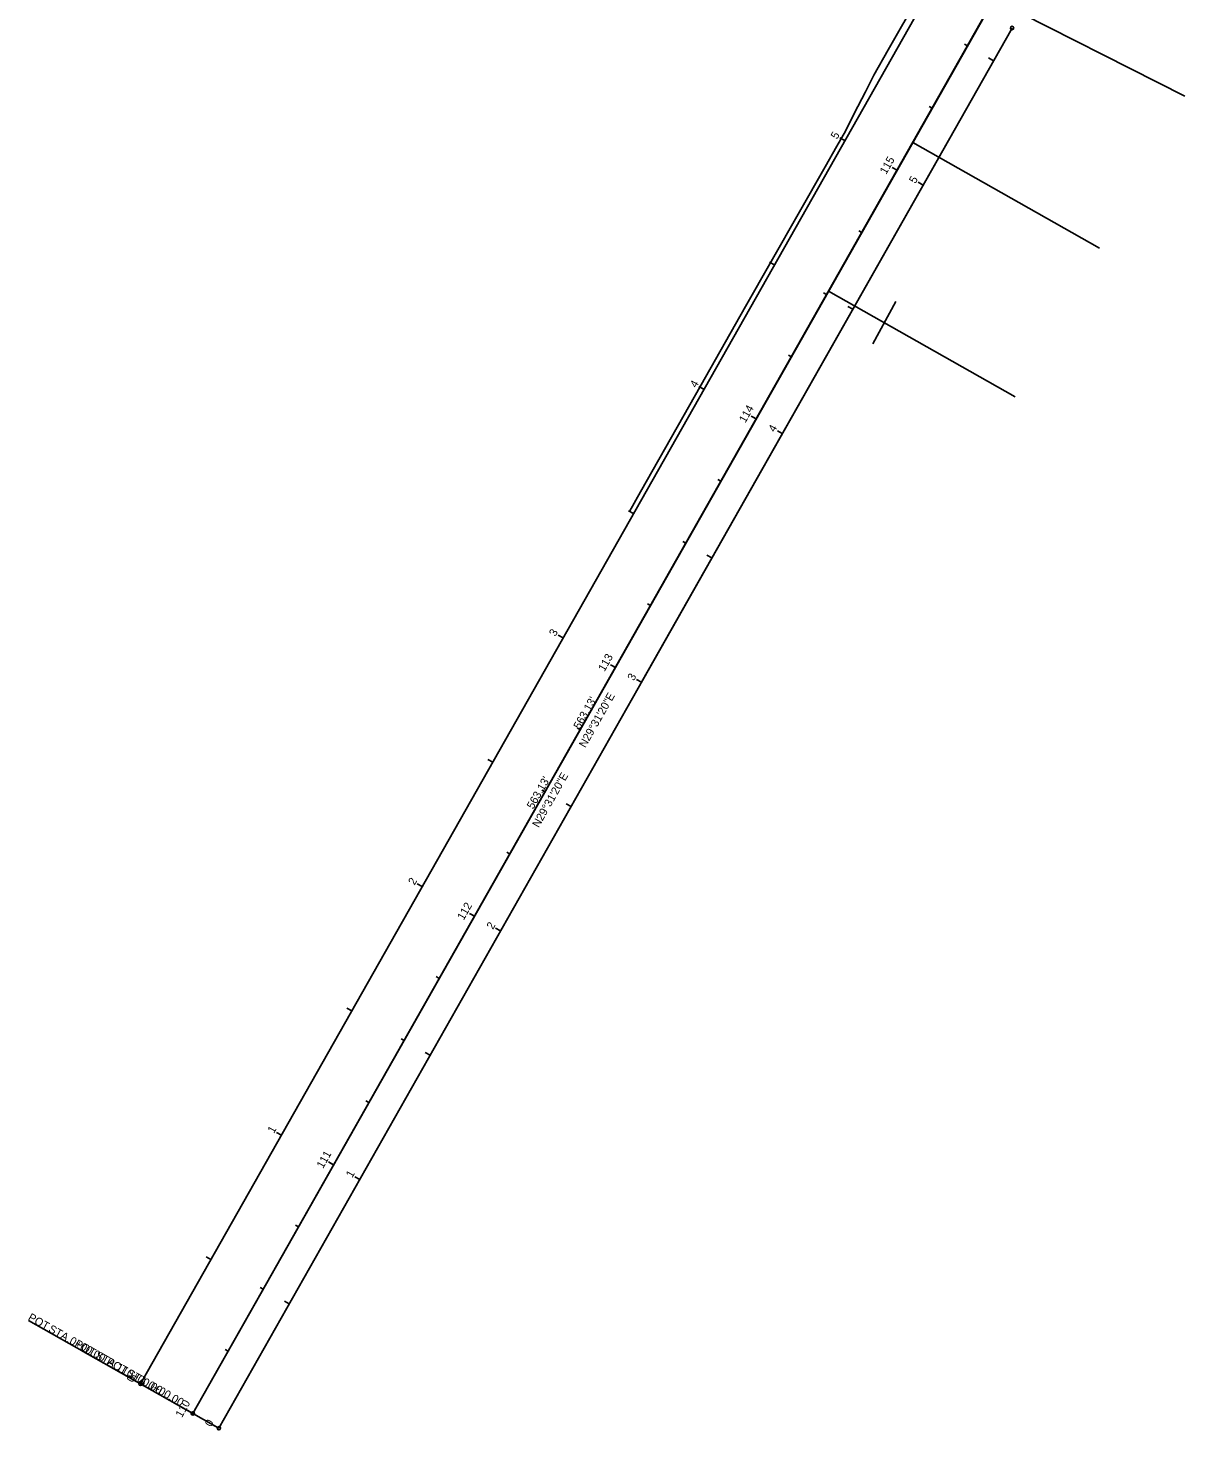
# Model space of a CAD drawing. Extents: x 1363416 to 1365241, y 422393 to 423801.
# Drawn here: x 1363842.2 to 1364246.9, y 422393.2 to 422883.8 of the extents above; entities that cross this region are included whole.
import ezdxf

# ---------------------------------------------------------------- set-up
doc = ezdxf.new("R2010")
doc.units = 0
for name, color, linetype in [('_CIVIL_CONSTRUCTION', 7, 'Continuous'), ('Default', 7, 'Continuous'), ('DT_X_Break_Line', 7, 'Continuous'), ('DT_X_Contour_Major', 7, 'Continuous'), ('DT_X_Contour_Minor', 7, 'Continuous'), ('DT_X_Island', 7, 'Continuous'), ('DT_X_Triangles', 7, 'Continuous'), ('MD_P_CURB_FACE_FL', 7, 'Continuous'), ('MD_P_CURB_FACE_TOP', 7, 'Continuous'), ('MD_P_PGL', 7, 'Continuous'), ('MD_P_SAWCUT', 7, 'Continuous'), ('PF_X_Ground_Line', 7, 'Continuous')]:
    doc.layers.add(name, color=color, linetype=linetype)

msp = doc.modelspace()

# ---------------------------------------------------------------- linework, layer by layer
at = {"layer": '_CIVIL_CONSTRUCTION'}
msp.add_line((1363899.82, 422398.95), (1364177.31, 422888.96), dxfattribs=at)
at = {"layer": 'Default'}
for p, q in [((1363899.82, 422398.95), (1364232.49, 422986.41)), ((1364145.75, 422788.04), (1364137.78, 422773.25))]:
    msp.add_line(p, q, dxfattribs=at)
at = {"layer": 'DT_X_Break_Line'}
for p, q in [((1363881.54, 422409.29), (1364159.03, 422899.31)), ((1363881.54, 422409.29), (1364159.03, 422899.31)), ((1364143.09, 422876.17), (1364154.79, 422896.72)), ((1363908.95, 422393.77), (1364186.44, 422883.79)), ((1363908.95, 422393.77), (1364186.44, 422883.79)), ((1363908.95, 422393.77), (1364186.44, 422883.79)), ((1364056.78, 422654.82), (1364186.44, 422883.79)), ((1364056.78, 422654.82), (1364186.44, 422883.79)), ((1364138.03, 422867.25), (1364143.09, 422876.17)), ((1364179.97, 422872.36), (1364178.23, 422873.35)), ((1364135.11, 422861.49), (1364138.03, 422867.25)), ((1364131.23, 422853.85), (1364135.11, 422861.49)), ((1364128.13, 422847.75), (1364131.23, 422853.85)), ((1364125.19, 422842.4), (1364128.13, 422847.75)), ((1364121.01, 422835.23), (1364125.19, 422842.4)), ((1364127.92, 422844.38), (1364126.18, 422845.36)), ((1364093.13, 422786.35), (1364121.01, 422835.23)), ((1364155.34, 422828.85), (1364153.59, 422829.84)), ((1364103.29, 422800.87), (1364101.55, 422801.85)), ((1364075.67, 422755.48), (1364093.13, 422786.35)), ((1364130.7, 422785.35), (1364128.96, 422786.33)), ((1364056.43, 422721.47), (1364075.67, 422755.48)), ((1364078.65, 422757.36), (1364076.91, 422758.35)), ((1364106.06, 422741.84), (1364104.32, 422742.82)), ((1364052.62, 422714.64), (1364056.43, 422721.47)), ((1364054.01, 422713.85), (1364052.27, 422714.84)), ((1364081.42, 422698.33), (1364079.68, 422699.31)), ((1364029.37, 422670.34), (1364027.63, 422671.33)), ((1364056.78, 422654.82), (1364055.04, 422655.81)), ((1364004.73, 422626.84), (1364002.99, 422627.82)), ((1364032.14, 422611.31), (1364030.4, 422612.3)), ((1363980.1, 422583.33), (1363978.36, 422584.31)), ((1364007.51, 422567.8), (1364005.77, 422568.79)), ((1363955.46, 422539.82), (1363953.72, 422540.8)), ((1363982.87, 422524.3), (1363981.13, 422525.28)), ((1363930.82, 422496.31), (1363929.08, 422497.3)), ((1363958.23, 422480.79), (1363956.49, 422481.77)), ((1363906.18, 422452.8), (1363904.44, 422453.79)), ((1363933.59, 422437.28), (1363931.85, 422438.27)), ((1363881.54, 422409.29), (1363842.39, 422431.47)), ((1363908.95, 422393.77), (1363869.8, 422415.95)), ((1363881.54, 422409.29), (1363879.8, 422410.28)), ((1363908.95, 422393.77), (1363907.21, 422394.76))]:
    msp.add_line(p, q, dxfattribs=at)
for centre in [(1364186.44, 422883.79), (1363881.54, 422409.29), (1363908.95, 422393.77)]:
    msp.add_circle(centre, 0.6, dxfattribs=at)
at = {"layer": 'DT_X_Contour_Major'}
for p, q in [((1364170.84, 422877.54), (1364169.79, 422878.13)), ((1364158.52, 422855.78), (1364157.47, 422856.37)), ((1364146.2, 422834.03), (1364144.46, 422835.01)), ((1364133.88, 422812.27), (1364132.84, 422812.87)), ((1364121.56, 422790.52), (1364120.52, 422791.11)), ((1364109.24, 422768.77), (1364108.2, 422769.36)), ((1364096.92, 422747.01), (1364095.18, 422748)), ((1364084.6, 422725.26), (1364083.56, 422725.85)), ((1364072.28, 422703.5), (1364071.24, 422704.09)), ((1364059.96, 422681.75), (1364058.92, 422682.34)), ((1364047.65, 422660), (1364045.91, 422660.98)), ((1364035.33, 422638.24), (1364034.28, 422638.83)), ((1364023.01, 422616.49), (1364021.96, 422617.08)), ((1364010.69, 422594.73), (1364009.64, 422595.32)), ((1363998.37, 422572.98), (1363996.63, 422573.96)), ((1363986.05, 422551.22), (1363985.01, 422551.82)), ((1363973.73, 422529.47), (1363972.69, 422530.06)), ((1363961.41, 422507.72), (1363960.37, 422508.31)), ((1363949.09, 422485.96), (1363947.35, 422486.95)), ((1363936.77, 422464.21), (1363935.73, 422464.8)), ((1363924.46, 422442.45), (1363923.41, 422443.05)), ((1363912.14, 422420.7), (1363911.09, 422421.29)), ((1363899.82, 422398.95), (1363898.08, 422399.93))]:
    msp.add_line(p, q, dxfattribs=at)
at = {"layer": 'DT_X_Island'}
for p, q in [((1364180.04, 422893.86), (1364246.92, 422859.91)), ((1364151.71, 422843.76), (1364216.97, 422806.8)), ((1364122.23, 422791.71), (1364187.49, 422754.75))]:
    msp.add_line(p, q, dxfattribs=at)
at = {"layer": 'DT_X_Triangles'}
msp.add_line((1363899.82, 422398.95), (1363860.66, 422421.12), dxfattribs=at)
msp.add_circle((1363899.82, 422398.95), 0.6, dxfattribs=at)
at = {"layer": 'MD_P_CURB_FACE_TOP'}
msp.add_line((1363899.82, 422398.95), (1363860.66, 422421.12), dxfattribs=at)
msp.add_circle((1363899.82, 422398.95), 0.6, dxfattribs=at)
at = {"layer": 'MD_P_SAWCUT'}
for p, q in [((1364146.2, 422834.03), (1364144.46, 422835.01)), ((1364096.92, 422747.01), (1364095.88, 422747.6)), ((1364047.65, 422660), (1364046.6, 422660.59)), ((1363998.37, 422572.98), (1363997.33, 422573.57)), ((1363949.09, 422485.96), (1363948.05, 422486.55)), ((1363899.82, 422398.95), (1363898.08, 422399.93))]:
    msp.add_line(p, q, dxfattribs=at)

# ---------------------------------------------------------------- texts
at = {"layer": 'DT_X_Break_Line'}
for s, rotation, p in [('5', 60.4777, (1364125.22, 422844.68)), ('5', 60.4777, (1364152.63, 422829.15)), ('4', 60.4777, (1364075.96, 422757.69)), ('4', 60.4777, (1364103.37, 422742.17)), ('3', 60.4777, (1364026.69, 422670.67)), ('3', 60.4777, (1364054.1, 422655.15)), ('2', 60.4777, (1363977.41, 422583.65)), ('2', 60.4777, (1364004.82, 422568.13)), ('1', 60.4777, (1363928.19, 422496.75)), ('1', 60.4777, (1363955.6, 422481.22)), ('POT', 330.4777, (1363841.92, 422431.78)), (' STA. ', 330.4777, (1363848.18, 422428.23)), ('0+00.00', 330.4777, (1363856.41, 422423.58)), ('POT', 330.4777, (1363869.33, 422416.26)), ('0', 60.4777, (1363878.82, 422409.56)), (' STA. ', 330.4777, (1363875.59, 422412.71)), ('0+00.00', 330.4777, (1363883.82, 422408.06)), ('0', 60.4777, (1363906.23, 422394.04))]:
    msp.add_text(s, height=2.8, rotation=rotation, dxfattribs=at).set_placement(p)
at = {"layer": 'DT_X_Contour_Major'}
for s, p in [('115', (1364142.39, 422832.38)), ('114', (1364093.13, 422745.4)), ('113', (1364043.86, 422658.38)), ('112', (1363994.58, 422571.36)), ('111', (1363945.37, 422484.45)), ('110', (1363895.99, 422397.27))]:
    msp.add_text(s, height=2.8, rotation=60.4777, dxfattribs=at).set_placement(p)
at = {"layer": 'DT_X_Contour_Minor'}
msp.add_text("563.13'", height=2.8, rotation=60.4777, dxfattribs=at).set_placement((1364018.91, 422610.23))
at = {"layer": 'DT_X_Triangles'}
for s, p in [('POT', (1363858.24, 422422.54)), (' STA. ', (1363864.51, 422418.99)), ('110+00.00', (1363872.74, 422414.33))]:
    msp.add_text(s, height=2.8, rotation=330.4777, dxfattribs=at).set_placement(p)
at = {"layer": 'MD_P_CURB_FACE_FL'}
msp.add_text('N29°31\'20"E', height=2.8, rotation=60.4777, dxfattribs=at).set_placement((1364037.14, 422631.7))
at = {"layer": 'MD_P_CURB_FACE_TOP'}
for s, p in [('POT', (1363858.24, 422422.54)), (' STA. ', (1363864.51, 422418.99)), ('110+00.00', (1363872.74, 422414.33))]:
    msp.add_text(s, height=2.8, rotation=330.4777, dxfattribs=at).set_placement(p)
at = {"layer": 'MD_P_PGL'}
msp.add_text("563.13'", height=2.8, rotation=60.4777, dxfattribs=at).set_placement((1364035.23, 422638.16))
at = {"layer": 'MD_P_SAWCUT'}
for s, p in [('115', (1364142.39, 422832.38)), ('110', (1363895.99, 422397.27))]:
    msp.add_text(s, height=2.8, rotation=60.4777, dxfattribs=at).set_placement(p)
at = {"layer": 'PF_X_Ground_Line'}
msp.add_text('N29°31\'20"E', height=2.8, rotation=60.4777, dxfattribs=at).set_placement((1364020.82, 422603.76))

doc.saveas('drawing.dxf')
